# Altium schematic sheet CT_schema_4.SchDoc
size 300 x 177 mm
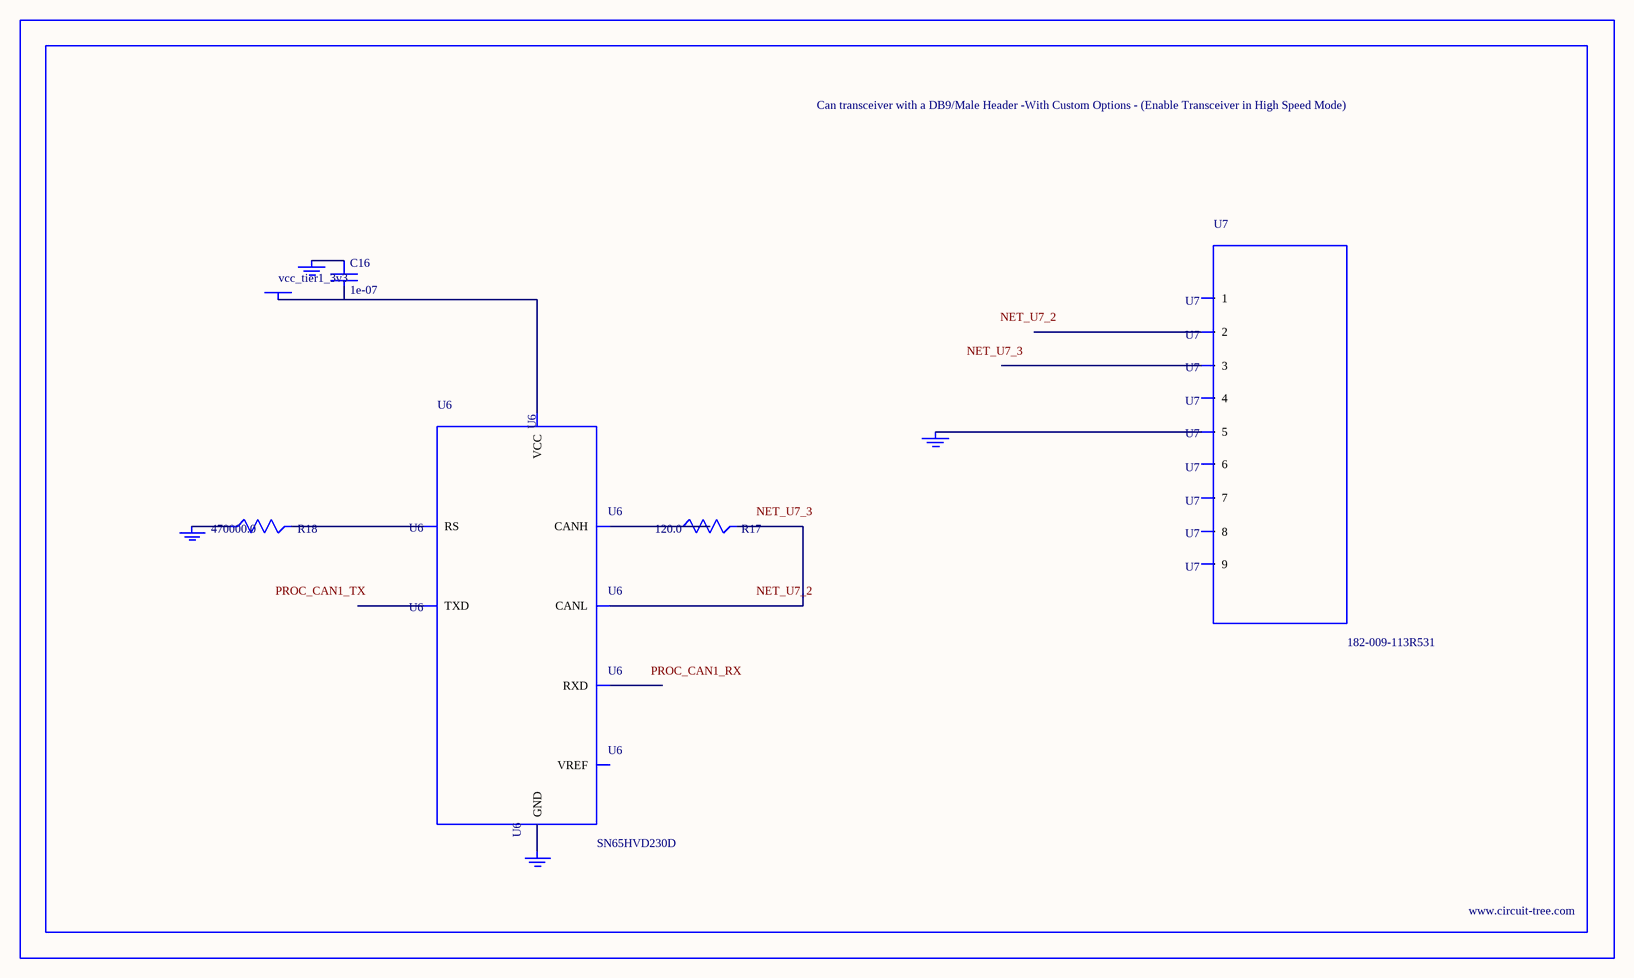
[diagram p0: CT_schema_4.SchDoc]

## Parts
BORDER3  (no value)
C16  1e-07  [C0402]
GND_INSTANCE_3_0  (no value)
GND_INSTANCE_3_1  (no value)
GND_INSTANCE_3_2  (no value)
GND_INSTANCE_3_3  (no value)
POWER_INSTANCE_3_0  vcc_tier1_3v3
R17  120.0  [R0603]
R18  470000.0  [R0603]
U6  SN65HVD230D  [SOIC-8]
U7  182-009-113R531  [182-009-MALE]

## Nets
NetC16_1: C16.1 GND_INSTANCE_3_0.0(GND)
NetC16_2: C16.2 POWER_INSTANCE_3_0.0(PWR) U6.3(VCC)
NetGND_INSTANCE_3_1_0: GND_INSTANCE_3_1.0(GND) R18.1
NetGND_INSTANCE_3_2_0: GND_INSTANCE_3_2.0(GND) U6.2(GND)
NetGND_INSTANCE_3_3_0: GND_INSTANCE_3_3.0(GND) U7.5
NetR17_1: R17.1 U6.7(CANH)
NetR17_2: R17.2 U6.6(CANL)
NetR18_2: R18.2 U6.8(RS)

Not connected (* = marked no-connect by the designer): U6 1(TXD) 4(RXD) 5(VREF); U7 1 2 3 4 6 7 8 9

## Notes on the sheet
- Labels drawn without touching a wire or pin: NET_U7_2, NET_U7_3, PROC_CAN1_RX, PROC_CAN1_TX

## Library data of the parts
BORDER3 = BORDER_PAGE3
C16 = C0402C104K3RACTU
GND_INSTANCE_3_0-GND_INSTANCE_3_3 = GND
POWER_INSTANCE_3_0 = PWR
R17 = RC0603JR-07120RL
R18 = RC0603JR-07470KL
